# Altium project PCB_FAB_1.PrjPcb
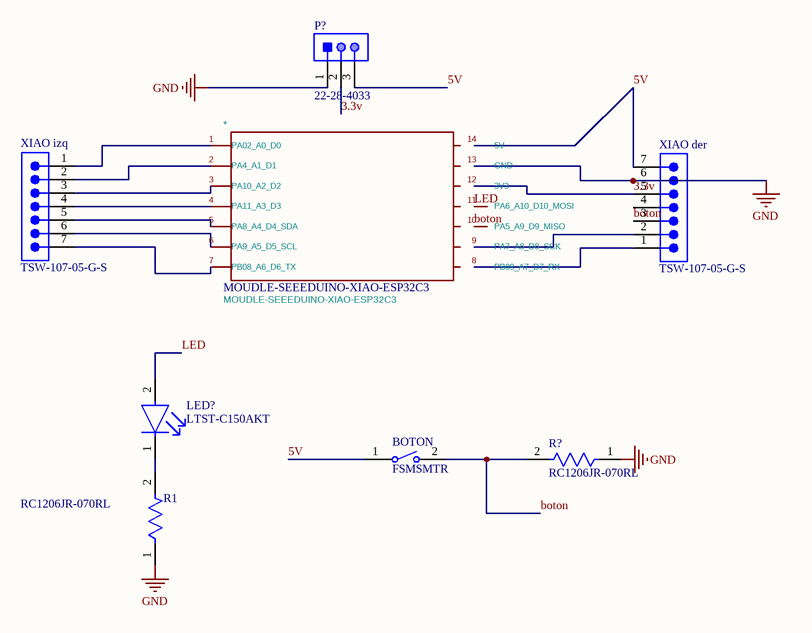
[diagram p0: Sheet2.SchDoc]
1 sheet, 8 parts. Net scope: global (net labels, ports and power ports of the same name join across sheets).
Board file: PCB1.PcbDoc

## Sheet Sheet2.SchDoc
size A4; SheetNumber: 1; SheetTotal: 1

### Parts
*  MOUDLE-SEEEDUINO-XIAO-ESP32C3  [MOUDLE14P-SMD-2.54-21X17.8MM]
BOTON  FSMSMTR  [TECO-FSMSMTR_V]
LED?  LTST-C150AKT  [FP-LTST-C150AKT-MFG]
P?  22-28-4033  [MOLX-22-28-4033_V]
R1  RC1206JR-070RL  [FP-RC1206-MFG]
R?  RC1206JR-070RL  [FP-RC1206-MFG]
XIAO_der  TSW-107-05-G-S  [SMTC-TSW-107-05-X-S]
XIAO_izq  TSW-107-05-G-S  [SMTC-TSW-107-05-X-S]

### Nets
GND: *.13(GND) P?.1 R1.1 R?.1 XIAO_der.6
3.3v: *.12(3V3) P?.2 XIAO_der.5
5V: *.14(5V) BOTON.1 P?.3 XIAO_der.7
boton: *.10(PA5_A9_D9_MISO) BOTON.2 R?.2 XIAO_der.3
LED: *.11(PA6_A10_D10_MOSI) LED?.2(A)
Net*_1: *.1(PA02_A0_D0) XIAO_izq.1
Net*_2: *.2(PA4_A1_D1) XIAO_izq.2
Net*_3: *.3(PA10_A2_D2) XIAO_izq.3
Net*_4: *.4(PA11_A3_D3) XIAO_izq.4
Net*_5: *.5(PA8_A4_D4_SDA) XIAO_izq.5
Net*_6: *.6(PA9_A5_D5_SCL) XIAO_izq.6
Net*_7: *.7(PB08_A6_D6_TX) XIAO_izq.7
Net*_8: *.8(PB09_A7_D7_RX) XIAO_der.1
Net*_9: *.9(PA7_A8_D8_SCK) XIAO_der.2
NetLED?_1: LED?.1(C) R1.2

Not connected (* = marked no-connect by the designer): XIAO_der 4

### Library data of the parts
BOTON = CMP-2000-07501-1: FSMSM Push Button Switch, 50 mA, -35 to 85 degC, 2-Pin SMD, RoHS, Tape and Reel; Manufacturer: TE Connectivity; Voltage Rating (DC): 24V; Electrical Life: 20000Cycles; Operating Force: 180gf; Switch Travel: 0.25mm; Contact Current Rating: 50mA; Case\/Package: SMD/SMT; Actuator Length: 1.07mm; Throw Configuration: SPST; Actuator Material: Polyamide; Contact Resistance: 100mOhm; Illumination Type: Illuminated; Max Voltage Rating (DC): 12V
LED? = CMP-22017-000004-1: LED AMBER CLEAR SMD; Manufacturer: Lite-On; Luminous Intensity: 6mcd; Viewing Angle: 130°; Wavelength: 602nm; Reverse Voltage: 5V; Forward Current: 30mA; Led Orientation: Top View; Power Dissipation: 100mW; Peak Emmision Wavelength: 610nm; Forward Voltage: 2.1V
P? = CMP-1676-00001-5: Male Header, Pitch 2.54 mm, 1 x 3 Position, Height 8.38 mm, Tail Length 3.18 mm, RoHS, Bulk; Manufacturer: Molex; Rows: 1; Voltage Rating: 250 V; Current Rating: 4 A
R1 R? = CMP-2100-03681-2: RES SMD 0 OHM JUMPER 1/4W 1206; Manufacturer: YAGEO; Voltage Rating: 200V; Temperature Coefficient: 300ppm/°C; Power Rating: 0.25W; Value: 0Ω; Tolerance: 5%
XIAO_der XIAO_izq = CMP-1024-00400-1: 0.025" SQ Post Header, Through-hole, Vertical, -55 to 125 degC, 2.54 mm Pitch, 7-Pin, Male, RoHS; Manufacturer: Samtec; Pitch: 2.54 mm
